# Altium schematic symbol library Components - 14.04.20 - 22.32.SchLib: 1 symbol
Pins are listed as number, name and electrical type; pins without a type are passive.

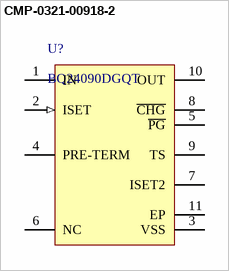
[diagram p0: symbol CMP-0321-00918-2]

## CMP-0321-00918-2
designator U?, comment BQ24090DGQT
1 A, Single Input, Single Cell Li-Ion Battery Charger with 10 K ohm NTC, 4.5 V, -40 to 150 degC, 10-pin MSOP-PowerPAD (DGQ), Green (RoHS & no Sb/Br); Manufacturer: Texas Instruments; NiCd: N; SubFamily: Battery Charge Management; Vin(Min)(V): 4.5
footprint DGQ0010D_M (TSOP, 10-Leads, Body 3.1x3.1mm, Pitch 0.5mm, Thermal Pad 1.88x1.57mm, IPC Low Density)
footprint DGQ0010D_N (TSOP, 10-Leads, Body 3.1x3.1mm, Pitch 0.5mm, Thermal Pad 1.88x1.57mm, IPC Medium Density)
footprint DGQ0010D_L (TSOP, 10-Leads, Body 3.1x3.1mm, Pitch 0.5mm, Thermal Pad 1.88x1.57mm, IPC High Density)
pins: 1 IN (power) "Input power, connected to external DC supply (AC adapter or USB port). Expected range of bypass capacitors 1uF to 10uF, connect from IN to VSS.", 2 ISET (in) "Programs the Fast-charge current setting. External resistor from ISET to VSS defines fast charge current value. Range is 10.8k (50mA) to 675 ohm (800mA).", 3 VSS (power) "Ground terminal", 4 PRE-TERM "Programs the Current Termination Threshold (5 to 50% of Iout which is set by ISET) and Sets the Pre- Charge Current to twice the Termination Current Level. Expected range of programming resistor is 1k to 10kohm (2k: Ipgm/10 (See Datasheet)", 5 ~{PG} (hiz) "Low (FET on) indicates the input voltage is above UVLO and the OUT (battery) voltage.", 6 NC "Do not make a connection to this pin (for internal use) - Do not route through this pin", 7 ISET2 "Programming the Input/Output Current Limit for the USB or Adaptor source: High = 500mAmax, Low = ISET, FLOAT = 100mA max.", 8 ~{CHG} (hiz) "Low (FET on) indicates charging and Open Drain (FET off) indicates no Charging or Charge complete.", 9 TS "Temperature sense pin connected to bq24090/2 -10k at 25degreesC NTC thermistor & bq24091/3 -100k at 25degreesC NTC thermistor, in the battery pack. Floating TS Pin or pulling High puts part in TTDM “Charger?Mode and disable (See Datasheet)", 10 OUT (power) "Battery Connection. System Load may be connected. Average load should not be excessive, allowing battery to charge within the 10 hour safety timer window. Expected range of bypass capacitors 1uF to 10uF.", 11 EP (power) "There is an internal electrical connection between the exposed thermal pad and the VSS pin of the device. The thermal pad must be connected to the same potential as the VSS pin on the printed circuit board. Do not use the (See Datasheet)"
